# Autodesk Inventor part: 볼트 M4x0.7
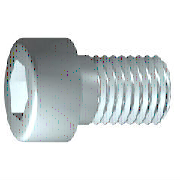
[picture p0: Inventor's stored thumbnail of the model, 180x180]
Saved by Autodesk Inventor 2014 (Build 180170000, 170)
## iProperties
IsCustomPart: 1
Created: 2015-10
Part Number: 볼트 M4x0.7
Material: 스테인리스강
Description: 6각머리 태핑 나사
Document SubType Name: Modeling
Standard: KS B 1003
Designer: mdu
Standards Organization: KS
Language: ko-KR
Size Designation: M 4 x 16
Categories: <MemberInstance><Categories><Category DisplayName="조임쇠" InternalName="e4da775c-781d-43d5-af7c-5136215cf5a6" Mnemonic="FSTN"><Category DisplayName="볼트" InternalN
Density: 8.08 g/cm^3
Mass: 2.70334 g
Surface Area: 3.81118 cm^2
Volume: 0.334572 cm^3
Appearance: 반광택
Author: mdu
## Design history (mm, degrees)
sketch "스케치1"
  geometry: L1 (-1, 0)-(16, 0); L2 (16, 0)-(16, 2); L3 (16, 2)-(1.75, 2); L4 (1.75, 2)-(1.32, 2); L5 (1.32, 2)-(0, 2); L6 (0, 2)-(0, 3.5); L7 (0, 3.5)-(-4, 3.5); L8 (-4, 3.5)-(-4, 1.732); L9 (-4, 1.732)-(-2, 1.732); L10 (-2, 1.732)-(-1, 0); L11 (-8, 0)-(20, 0) reference; L12 (0, -0.7)-(0, 4.2) reference; L13 (1.75, 2)-(0, 2)
  constraints: 22 end point, 6 parallel, 2 collinear, 2 perpendicular, 1 horizontal, 1 point on line
  dimensions: "d1" = 14.25 distance from line of L3.end L2 (= GEL); "d2" = 0.42952 distance of L4.end L3.end (computed from GAL); "d3" = 4 distance between parallel lines of L8 L6 (= KOH); "d4" = 2 distance of L8.end L9.end (= INTI); "d5" = 60 deg angle of L10 L1; "d6" = 4 diameter of L3 L1 (= GD); "d7" = 4 diameter of L5 L1 (= BDM); "d8" = 3.4641 diameter of L9 L1 (= 1.1547 x SW); "d9" = 7 diameter of L7 L1 (= KOD); "d26" = 16 distance between parallel lines of L12 L2 (= NLG)
revolve "본체" sketch "스케치1" stored, may be unused: angle "d10" = 90 deg
sketch "스케치2"
  geometry: L1 (0, -4.9)-(0, 4.9) reference; L2 (-4.9, 0)-(4.9, 0) reference; L3 (1.732, 0)-(0.866, -1.5); L4 (0.866, -1.5)-(-0.866, -1.5); L5 (-0.866, -1.5)-(-1.732, 0); L6 (-1.732, 0)-(-0.866, 1.5); L7 (-0.866, 1.5)-(0.866, 1.5); L8 (0.866, 1.5)-(1.732, 0); 2 further points
  constraints: 12 end point, 1 coincident, 1 horizontal alignment, 1 point on line, 12 other
extrude "슬롯" join sketch "스케치2" stored distance "d11" = 10; taper "d12" = 0 deg
workplane "Work Plane1"
fillet "Fillet2" dims "d30" = 0.1 (= R)
body "Solid1"
fillet "모깎기1" dims "d17" = 0.4 (= RR)
feature "스레드" dims "d13" = 14.25 (= GEL), "d14" = 0
chamfer "모따기1" distance "d15" = 0.42941 (= -0.5 x SPD + 0.5 x GD); stored, may be unused: second distance "d16" = 0.42941 (= GUL), angle "d27" = 45 deg
other parameters: "GD" = 4 (= NND) [user parameter; used in 2 equation terms], "NLG" = 16 [user parameter; used in 1 equation term], "GEL" = 14.25 [user parameter; used in 2 equation terms], "KOD" = 7 [user parameter; used in 1 equation term], "KOH" = 4 [user parameter; used in 1 equation term], "INTI" = 2 [user parameter; used in 1 equation term], "GAL" = 0.42941 (= 0.61345 x PTC) [user parameter; used in 1 equation term], "GUL" = 0.42941 (= 0.61345 x PTC) [user parameter; used in 1 equation term], "BDM" = 4 (= NND) [user parameter; used in 1 equation term], "SW" = 3 [user parameter; used in 2 equation terms], "RR" = 0.4 [user parameter; used in 1 equation term], "SPD" = 3.14117 (= NND - 1.2269 x PTC) [user parameter; used in 1 equation term], "d19" = 0, "d28" = 0, "d29" = 0, "R" = 0.1 [user parameter; used in 1 equation term], "PHH" = 0.2 [user parameter], "GD1" = 3.14117 (= THREADDIA - 1.2269 x PTC) [user parameter], "THREADDIA" = 4 [user parameter; used in 1 equation term], "FAWI" = 45 deg [user parameter], "TPU" = 14.28571 (computed from PTC) [user parameter], "PTC" = 0.7 [user parameter; used in 5 equation terms], "NND" = 4 [user parameter; used in 3 equation terms], "TOA" = 30 deg [user parameter], "E0" = 3.465 (= 1.155 x SW) [user parameter]
